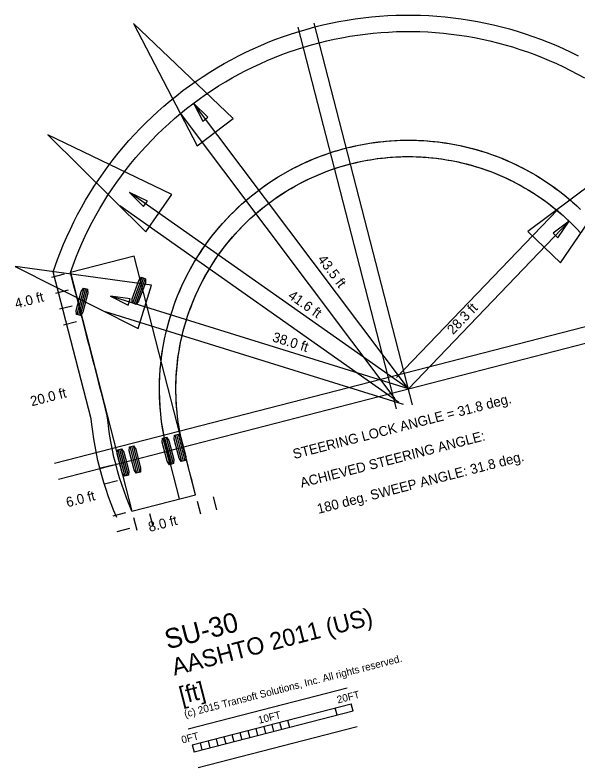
# Model space of a CAD drawing. Extents: x 916040 to 917457, y 328936 to 330267.
# Drawn here: x 916815.3 to 916883.8, y 329775.2 to 329866.9 of the extents above; entities that cross this region are included whole.
import ezdxf

# ---------------------------------------------------------------- set-up
doc = ezdxf.new("R2010")
doc.units = 0
doc.layers.add('SU_IntoDriveway', color=7, linetype='Continuous')

msp = doc.modelspace()

# ---------------------------------------------------------------- linework, layer by layer
at = {"layer": 'SU_IntoDriveway'}
for p, q in [((916863.656, 329819.438), (916851.67, 329865.925)), ((916861.719, 329818.939), (916849.734, 329865.426)), ((916863.156, 329821.375), (916836.984, 329856.161)), ((916861.558, 329820.172), (916835.385, 329854.959)), ((916863.156, 329821.375), (916829.176, 329845.317)), ((916862.004, 329819.74), (916828.024, 329843.682)), ((916861.713, 329822.759), (916881.3, 329843.183)), ((916863.156, 329821.375), (916882.743, 329841.799)), ((916829.742, 329837.545), (916821.995, 329835.548)), ((916837.231, 329808.495), (916829.742, 329837.545)), ((916821.22, 329835.348), (916819.671, 329834.948)), ((916821.995, 329835.548), (916829.485, 329806.497)), ((916821.995, 329835.548), (916821.995, 329835.548)), ((916830.699, 329834.958), (916829.559, 329831.826)), ((916830.895, 329834.887), (916829.755, 329831.755)), ((916831.091, 329834.816), (916829.951, 329831.683)), ((916820.043, 329812.325), (916905.271, 329834.298)), ((916823.627, 329833.654), (916822.767, 329830.433)), ((916823.828, 329833.6), (916822.968, 329830.379)), ((916824.029, 329833.546), (916823.169, 329830.326)), ((916821.72, 329833.411), (916820.17, 329833.012)), ((916863.156, 329821.375), (916826.867, 329832.673)), ((916820.542, 329810.388), (916905.77, 329832.361)), ((916822.219, 329831.474), (916820.67, 329831.075)), ((916862.562, 329819.465), (916826.272, 329830.763)), ((916822.718, 329829.538), (916821.169, 329829.138)), ((916833.26, 329815.388), (916834.092, 329812.16)), ((916833.461, 329815.44), (916834.293, 329812.212)), ((916833.663, 329815.492), (916834.495, 329812.264)), ((916834.712, 329815.763), (916835.544, 329812.535)), ((916834.914, 329815.815), (916835.746, 329812.587)), ((916835.116, 329815.867), (916835.948, 329812.639)), ((916829.225, 329814.348), (916830.057, 329811.12)), ((916829.427, 329814.4), (916830.259, 329811.172)), ((916829.628, 329814.452), (916830.46, 329811.224)), ((916827.772, 329813.973), (916828.604, 329810.746)), ((916827.974, 329814.025), (916828.806, 329810.798)), ((916828.176, 329814.077), (916829.008, 329810.85)), ((916827.212, 329812.108), (916825.663, 329811.708)), ((916827.711, 329810.171), (916826.162, 329809.772)), ((916829.485, 329806.497), (916837.231, 329808.495)), ((916839.368, 329808.219), (916839.767, 329806.67)), ((916837.431, 329807.72), (916837.83, 329806.171)), ((916828.71, 329806.298), (916827.161, 329805.898)), ((916831.621, 329806.222), (916832.02, 329804.673)), ((916829.684, 329805.723), (916830.084, 329804.173)), ((916829.209, 329804.361), (916827.66, 329803.962)), ((916836.325, 329779.965), (916855.692, 329784.958)), ((916836.824, 329778.028), (916856.191, 329783.021)), ((916856.416, 329782.15), (916856.191, 329783.021)), ((916856.416, 329782.15), (916837.049, 329777.157)), ((916854.479, 329781.651), (916854.254, 329782.522)), ((916845.539, 329780.275), (916845.764, 329779.404)), ((916845.539, 329780.275), (916845.764, 329779.404)), ((916846.508, 329780.525), (916846.732, 329779.653)), ((916846.508, 329780.525), (916846.732, 329779.653)), ((916847.476, 329780.775), (916847.701, 329779.903)), ((916848.444, 329781.024), (916848.669, 329780.153)), ((916856.915, 329780.213), (916837.548, 329775.22)), ((916842.634, 329779.526), (916842.859, 329778.655)), ((916842.634, 329779.526), (916842.859, 329778.655)), ((916843.603, 329779.776), (916843.827, 329778.904)), ((916843.603, 329779.776), (916843.827, 329778.904)), ((916844.571, 329780.026), (916844.796, 329779.154)), ((916844.571, 329780.026), (916844.796, 329779.154)), ((916838.761, 329778.528), (916838.986, 329777.656)), ((916838.761, 329778.528), (916838.986, 329777.656)), ((916839.729, 329778.777), (916839.954, 329777.906)), ((916839.729, 329778.777), (916839.954, 329777.906)), ((916840.698, 329779.027), (916840.922, 329778.156)), ((916840.698, 329779.027), (916840.922, 329778.156)), ((916841.666, 329779.277), (916841.891, 329778.405)), ((916841.666, 329779.277), (916841.891, 329778.405)), ((916836.824, 329778.028), (916837.049, 329777.157)), ((916837.793, 329778.278), (916838.017, 329777.407))]:
    msp.add_line(p, q, dxfattribs=at)
for points in [[(916827.636, 329805.734), (916827.302, 329806.543), (916826.965, 329807.379), (916826.643, 329808.237), (916826.336, 329809.116), (916826.068, 329809.99), (916825.811, 329810.854), (916825.571, 329811.738), (916825.349, 329812.641), (916825.164, 329813.532), (916824.991, 329814.408), (916824.832, 329815.31), (916824.711, 329816.192), (916824.598, 329817.048), (916824.517, 329817.752), (916819.905, 329835.642), (916820.439, 329837.139), (916820.795, 329838.071), (916821.171, 329838.996), (916821.567, 329839.912), (916821.984, 329840.82), (916822.42, 329841.717), (916822.876, 329842.606), (916823.351, 329843.484), (916823.845, 329844.351), (916824.358, 329845.207), (916824.89, 329846.052), (916825.44, 329846.885), (916826.008, 329847.706), (916826.594, 329848.514), (916827.198, 329849.309), (916827.819, 329850.09), (916828.457, 329850.858), (916829.112, 329851.612), (916829.783, 329852.351), (916830.47, 329853.075), (916831.173, 329853.784), (916831.891, 329854.478), (916832.624, 329855.155), (916833.372, 329855.816), (916834.134, 329856.461), (916834.911, 329857.089), (916835.7, 329857.7), (916836.503, 329858.293), (916837.319, 329858.868), (916838.147, 329859.426), (916838.988, 329859.965), (916839.839, 329860.486), (916840.702, 329860.987), (916841.576, 329861.47), (916842.461, 329861.934), (916843.355, 329862.378), (916844.259, 329862.802), (916845.171, 329863.206), (916846.093, 329863.591), (916847.022, 329863.955), (916847.96, 329864.298), (916848.905, 329864.621), (916849.856, 329864.923), (916850.814, 329865.204), (916851.778, 329865.464), (916852.747, 329865.703), (916853.722, 329865.921), (916854.701, 329866.117), (916855.684, 329866.292), (916856.67, 329866.445), (916857.66, 329866.576), (916858.652, 329866.686), (916859.647, 329866.773), (916860.643, 329866.839), (916861.641, 329866.884), (916862.639, 329866.906), (916863.637, 329866.906), (916864.635, 329866.885), (916865.633, 329866.842), (916866.629, 329866.776), (916867.624, 329866.689), (916868.616, 329866.58), (916869.606, 329866.45), (916870.593, 329866.298), (916871.576, 329866.124), (916872.555, 329865.928), (916873.53, 329865.712), (916874.499, 329865.474), (916875.463, 329865.214), (916876.422, 329864.934), (916877.373, 329864.633), (916878.318, 329864.31), (916879.256, 329863.968), (916880.186, 329863.604), (916881.108, 329863.221), (916882.021, 329862.817), (916882.925, 329862.394), (916883.82, 329861.95)], [(916829.485, 329806.497), (916829.154, 329807.299), (916828.829, 329808.105), (916828.523, 329808.918), (916828.237, 329809.739), (916827.983, 329810.568), (916827.735, 329811.401), (916827.507, 329812.239), (916827.299, 329813.083), (916827.125, 329813.929), (916826.957, 329814.776), (916826.809, 329815.62), (916826.693, 329816.459), (916826.583, 329817.293), (916826.489, 329818.118), (916826.275, 329818.948), (916826.061, 329819.778), (916825.847, 329820.608), (916825.633, 329821.438), (916825.419, 329822.268), (916825.205, 329823.098), (916824.991, 329823.928), (916824.777, 329824.758), (916824.563, 329825.588), (916824.349, 329826.418), (916824.135, 329827.248), (916823.921, 329828.078), (916823.707, 329828.908), (916823.493, 329829.738), (916823.279, 329830.568), (916823.065, 329831.398), (916822.851, 329832.228), (916822.637, 329833.058), (916822.423, 329833.888), (916822.209, 329834.718), (916821.995, 329835.548), (916821.995, 329835.548), (916822.316, 329836.446), (916822.656, 329837.338), (916823.015, 329838.222), (916823.394, 329839.098), (916823.792, 329839.965), (916824.209, 329840.824), (916824.645, 329841.673), (916825.099, 329842.512), (916825.572, 329843.342), (916826.062, 329844.16), (916826.571, 329844.968), (916827.097, 329845.764), (916827.64, 329846.549), (916828.2, 329847.322), (916828.778, 329848.082), (916829.371, 329848.829), (916829.981, 329849.563), (916830.607, 329850.284), (916831.249, 329850.99), (916831.906, 329851.683), (916832.578, 329852.361), (916833.264, 329853.024), (916833.965, 329853.671), (916834.68, 329854.304), (916835.409, 329854.92), (916836.151, 329855.52), (916836.906, 329856.104), (916837.674, 329856.671), (916838.454, 329857.221), (916839.246, 329857.754), (916840.049, 329858.27), (916840.864, 329858.768), (916841.689, 329859.247), (916842.524, 329859.709), (916843.37, 329860.152), (916844.225, 329860.577), (916845.089, 329860.982), (916845.961, 329861.369), (916846.842, 329861.736), (916847.731, 329862.084), (916848.627, 329862.413), (916849.531, 329862.721), (916850.44, 329863.01), (916851.356, 329863.279), (916852.278, 329863.528), (916853.205, 329863.756), (916854.136, 329863.964), (916855.072, 329864.152), (916856.012, 329864.319), (916856.955, 329864.465), (916857.902, 329864.59), (916858.85, 329864.695), (916859.801, 329864.779), (916860.754, 329864.842), (916861.707, 329864.885), (916862.661, 329864.906), (916863.616, 329864.906), (916864.57, 329864.886), (916865.524, 329864.844), (916866.477, 329864.782), (916867.427, 329864.699), (916868.376, 329864.595), (916869.323, 329864.47), (916870.266, 329864.324), (916871.206, 329864.158), (916872.142, 329863.971), (916873.074, 329863.764), (916874.001, 329863.536), (916874.923, 329863.289), (916875.839, 329863.02), (916876.749, 329862.732), (916877.652, 329862.424), (916878.549, 329862.097), (916879.438, 329861.749), (916880.319, 329861.383), (916881.193, 329860.997), (916882.057, 329860.592), (916882.912, 329860.168), (916883.758, 329859.726), (916884.594, 329859.265)], [(916833.791, 329813.829), (916833.638, 329814.454), (916833.494, 329815.103), (916833.364, 329815.755), (916833.249, 329816.41), (916833.148, 329817.067), (916833.061, 329817.726), (916832.989, 329818.387), (916832.931, 329819.049), (916832.888, 329819.712), (916832.859, 329820.376), (916832.845, 329821.041), (916832.846, 329821.706), (916832.861, 329822.37), (916832.891, 329823.034), (916832.935, 329823.697), (916832.993, 329824.36), (916833.066, 329825.02), (916833.154, 329825.679), (916833.256, 329826.336), (916833.372, 329826.99), (916833.503, 329827.642), (916833.648, 329828.29), (916833.807, 329828.936), (916833.98, 329829.577), (916834.167, 329830.215), (916834.368, 329830.848), (916834.583, 329831.477), (916834.812, 329832.101), (916835.054, 329832.72), (916835.31, 329833.333), (916835.579, 329833.941), (916835.862, 329834.543), (916836.157, 329835.138), (916836.466, 329835.726), (916836.787, 329836.308), (916837.121, 329836.882), (916837.467, 329837.449), (916837.826, 329838.009), (916838.197, 329838.56), (916838.58, 329839.103), (916838.975, 329839.638), (916839.381, 329840.163), (916839.799, 329840.68), (916840.228, 329841.187), (916840.668, 329841.685), (916841.119, 329842.173), (916841.58, 329842.651), (916842.052, 329843.119), (916842.534, 329843.577), (916843.026, 329844.023), (916843.528, 329844.459), (916844.038, 329844.884), (916844.559, 329845.297), (916845.088, 329845.699), (916845.625, 329846.09), (916846.172, 329846.468), (916846.726, 329846.834), (916847.288, 329847.188), (916847.858, 329847.53), (916848.435, 329847.859), (916849.02, 329848.175), (916849.611, 329848.479), (916850.208, 329848.769), (916850.812, 329849.046), (916851.422, 329849.31), (916852.037, 329849.561), (916852.658, 329849.798), (916853.283, 329850.021), (916853.914, 329850.231), (916854.549, 329850.426), (916855.188, 329850.608), (916855.831, 329850.775), (916856.477, 329850.929), (916857.127, 329851.068), (916857.779, 329851.193), (916858.435, 329851.304), (916859.092, 329851.4), (916859.751, 329851.482), (916860.412, 329851.549), (916861.074, 329851.602), (916861.738, 329851.641), (916862.402, 329851.664), (916863.066, 329851.674), (916863.73, 329851.668), (916864.394, 329851.648), (916865.058, 329851.614), (916865.72, 329851.565), (916866.382, 329851.501), (916867.042, 329851.423), (916867.699, 329851.331), (916868.355, 329851.224), (916869.008, 329851.103), (916869.659, 329850.967), (916870.306, 329850.818), (916870.95, 329850.654), (916871.59, 329850.476), (916872.226, 329850.284), (916872.858, 329850.078), (916873.485, 329849.858), (916874.107, 329849.625), (916874.724, 329849.378), (916875.335, 329849.118), (916875.94, 329848.844), (916876.539, 329848.557), (916877.132, 329848.257), (916877.718, 329847.944), (916878.297, 329847.619), (916878.869, 329847.28), (916879.433, 329846.93), (916879.99, 329846.567), (916880.538, 329846.191), (916881.078, 329845.804), (916881.609, 329845.405), (916882.132, 329844.995), (916882.645, 329844.573), (916883.149, 329844.14), (916883.643, 329843.697), (916884.128, 329843.242)], [(916835.295, 329807.995), (916833.793, 329813.821), (916833.581, 329814.7), (916833.394, 329815.598), (916833.234, 329816.501), (916833.101, 329817.409), (916832.995, 329818.32), (916832.918, 329819.235), (916832.867, 329820.151), (916832.845, 329821.068), (916832.85, 329821.985), (916832.883, 329822.902), (916832.944, 329823.817), (916833.032, 329824.73), (916833.148, 329825.64), (916833.292, 329826.546), (916833.462, 329827.447), (916833.66, 329828.342), (916833.885, 329829.232), (916834.136, 329830.113), (916834.415, 329830.987), (916834.719, 329831.852), (916835.049, 329832.708), (916835.405, 329833.553), (916835.787, 329834.387), (916836.193, 329835.209), (916836.624, 329836.018), (916837.08, 329836.814), (916837.559, 329837.595), (916838.059, 329838.359), (916838.441, 329838.908), (916838.832, 329839.446), (916839.234, 329839.976), (916839.648, 329840.496), (916840.073, 329841.007), (916840.51, 329841.509), (916840.957, 329842), (916841.415, 329842.482), (916841.883, 329842.954), (916842.362, 329843.416), (916842.851, 329843.866), (916843.349, 329844.306), (916843.857, 329844.735), (916844.374, 329845.153), (916844.9, 329845.559), (916845.435, 329845.954), (916845.979, 329846.336), (916846.531, 329846.707), (916847.09, 329847.066), (916847.658, 329847.412), (916848.233, 329847.745), (916848.815, 329848.066), (916849.404, 329848.374), (916849.999, 329848.669), (916850.601, 329848.951), (916851.209, 329849.22), (916851.822, 329849.475), (916852.441, 329849.717), (916853.066, 329849.945), (916853.695, 329850.159), (916854.328, 329850.36), (916854.966, 329850.546), (916855.608, 329850.719), (916856.253, 329850.877), (916856.902, 329851.022), (916857.554, 329851.152), (916858.208, 329851.267), (916858.865, 329851.369), (916859.524, 329851.455), (916860.184, 329851.528), (916860.846, 329851.586), (916861.509, 329851.629), (916862.173, 329851.658), (916862.837, 329851.672), (916863.502, 329851.672), (916864.166, 329851.657), (916864.83, 329851.627), (916865.493, 329851.583), (916866.155, 329851.525), (916866.815, 329851.452), (916867.474, 329851.364), (916868.131, 329851.262), (916868.785, 329851.146), (916869.436, 329851.015), (916870.085, 329850.871), (916870.73, 329850.712), (916871.371, 329850.538), (916872.009, 329850.351), (916872.642, 329850.15), (916873.271, 329849.935), (916873.895, 329849.706), (916874.513, 329849.464), (916875.126, 329849.208), (916875.734, 329848.939), (916876.335, 329848.657), (916876.93, 329848.361), (916877.519, 329848.053), (916878.1, 329847.731), (916878.675, 329847.397), (916879.241, 329847.051), (916879.801, 329846.692), (916880.352, 329846.321), (916880.895, 329845.938), (916881.429, 329845.543), (916881.954, 329845.136), (916882.471, 329844.718), (916882.978, 329844.289), (916883.476, 329843.849), (916883.964, 329843.398)], [(916835.733, 329814.305), (916835.586, 329814.908), (916835.451, 329815.514), (916835.33, 329816.124), (916835.222, 329816.735), (916835.128, 329817.349), (916835.047, 329817.965), (916834.979, 329818.582), (916834.926, 329819.201), (916834.885, 329819.82), (916834.859, 329820.441), (916834.845, 329821.061), (916834.846, 329821.682), (916834.86, 329822.303), (916834.888, 329822.923), (916834.929, 329823.543), (916834.984, 329824.161), (916835.052, 329824.778), (916835.134, 329825.394), (916835.229, 329826.007), (916835.338, 329826.618), (916835.46, 329827.227), (916835.595, 329827.833), (916835.744, 329828.436), (916835.905, 329829.035), (916836.08, 329829.631), (916836.268, 329830.222), (916836.469, 329830.81), (916836.682, 329831.392), (916836.909, 329831.97), (916837.148, 329832.543), (916837.399, 329833.111), (916837.663, 329833.673), (916837.939, 329834.229), (916838.227, 329834.778), (916838.527, 329835.322), (916838.839, 329835.858), (916839.162, 329836.388), (916839.498, 329836.91), (916839.844, 329837.425), (916840.202, 329837.932), (916840.571, 329838.432), (916840.95, 329838.923), (916841.34, 329839.405), (916841.741, 329839.879), (916842.152, 329840.344), (916842.573, 329840.8), (916843.004, 329841.247), (916843.445, 329841.684), (916843.895, 329842.111), (916844.354, 329842.528), (916844.823, 329842.935), (916845.3, 329843.332), (916845.786, 329843.718), (916846.28, 329844.093), (916846.782, 329844.458), (916847.292, 329844.811), (916847.81, 329845.153), (916848.335, 329845.484), (916848.868, 329845.803), (916849.407, 329846.111), (916849.952, 329846.406), (916850.504, 329846.689), (916851.063, 329846.961), (916851.627, 329847.22), (916852.196, 329847.466), (916852.771, 329847.7), (916853.351, 329847.921), (916853.935, 329848.13), (916854.524, 329848.326), (916855.117, 329848.508), (916855.714, 329848.678), (916856.314, 329848.835), (916856.918, 329848.978), (916857.525, 329849.108), (916858.134, 329849.225), (916858.746, 329849.328), (916859.36, 329849.418), (916859.976, 329849.495), (916860.593, 329849.558), (916861.212, 329849.607), (916861.831, 329849.643), (916862.451, 329849.665), (916863.072, 329849.674), (916863.692, 329849.669), (916864.313, 329849.65), (916864.932, 329849.618), (916865.551, 329849.572), (916866.169, 329849.513), (916866.785, 329849.44), (916867.399, 329849.353), (916868.012, 329849.254), (916868.622, 329849.14), (916869.229, 329849.014), (916869.834, 329848.874), (916870.435, 329848.721), (916871.033, 329848.555), (916871.627, 329848.376), (916872.217, 329848.183), (916872.803, 329847.978), (916873.384, 329847.76), (916873.96, 329847.53), (916874.531, 329847.286), (916875.096, 329847.031), (916875.656, 329846.763), (916876.209, 329846.483), (916876.757, 329846.19), (916877.298, 329845.886), (916877.832, 329845.57), (916878.359, 329845.243), (916878.878, 329844.904), (916879.39, 329844.553), (916879.895, 329844.192), (916880.391, 329843.819), (916880.879, 329843.436), (916881.358, 329843.042), (916881.829, 329842.638), (916882.291, 329842.223), (916882.743, 329841.799), (916883.191, 329841.36), (916883.637, 329840.903), (916884.082, 329840.429)], [(916837.231, 329808.495), (916837.017, 329809.325), (916836.803, 329810.155), (916836.589, 329810.985), (916836.375, 329811.815), (916836.161, 329812.645), (916835.947, 329813.475), (916835.733, 329814.305), (916835.533, 329815.138), (916835.358, 329815.977), (916835.208, 329816.821), (916835.084, 329817.669), (916834.986, 329818.52), (916834.913, 329819.374), (916834.866, 329820.23), (916834.845, 329821.086), (916834.85, 329821.943), (916834.881, 329822.799), (916834.938, 329823.654), (916835.02, 329824.507), (916835.128, 329825.357), (916835.262, 329826.203), (916835.422, 329827.045), (916835.606, 329827.882), (916835.816, 329828.712), (916836.051, 329829.536), (916836.311, 329830.352), (916836.595, 329831.16), (916836.904, 329831.959), (916837.237, 329832.748), (916837.593, 329833.527), (916837.973, 329834.295), (916838.375, 329835.051), (916838.801, 329835.794), (916839.248, 329836.524), (916839.718, 329837.24), (916839.718, 329837.24), (916839.718, 329837.24), (916840.072, 329837.751), (916840.437, 329838.253), (916840.813, 329838.747), (916841.199, 329839.233), (916841.597, 329839.711), (916842.004, 329840.179), (916842.422, 329840.639), (916842.85, 329841.089), (916843.287, 329841.53), (916843.734, 329841.96), (916844.191, 329842.382), (916844.656, 329842.792), (916845.131, 329843.193), (916845.614, 329843.583), (916846.105, 329843.962), (916846.605, 329844.331), (916847.112, 329844.688), (916847.628, 329845.035), (916848.15, 329845.37), (916848.68, 329845.693), (916849.217, 329846.004), (916849.761, 329846.304), (916850.311, 329846.592), (916850.867, 329846.867), (916851.429, 329847.131), (916851.997, 329847.382), (916852.57, 329847.62), (916853.149, 329847.846), (916853.732, 329848.059), (916854.319, 329848.259), (916854.911, 329848.447), (916855.507, 329848.621), (916856.106, 329848.782), (916856.709, 329848.93), (916857.315, 329849.065), (916857.923, 329849.186), (916858.535, 329849.294), (916859.148, 329849.389), (916859.763, 329849.47), (916860.38, 329849.537), (916860.998, 329849.591), (916861.618, 329849.632), (916862.238, 329849.659), (916862.858, 329849.672), (916863.479, 329849.672), (916864.099, 329849.658), (916864.719, 329849.63), (916865.339, 329849.589), (916865.957, 329849.535), (916866.574, 329849.466), (916867.189, 329849.385), (916867.802, 329849.289), (916868.413, 329849.181), (916869.022, 329849.059), (916869.627, 329848.923), (916870.23, 329848.775), (916870.829, 329848.613), (916871.424, 329848.438), (916872.016, 329848.251), (916872.603, 329848.05), (916873.186, 329847.836), (916873.763, 329847.61), (916874.336, 329847.371), (916874.904, 329847.12), (916875.465, 329846.856), (916876.021, 329846.58), (916876.571, 329846.292), (916877.114, 329845.991), (916877.65, 329845.679), (916878.18, 329845.356), (916878.702, 329845.021), (916879.216, 329844.674), (916879.724, 329844.316), (916880.223, 329843.947), (916880.713, 329843.568), (916881.196, 329843.177), (916881.67, 329842.777), (916882.134, 329842.366), (916882.59, 329841.944), (916883.036, 329841.513), (916883.474, 329841.073), (916883.902, 329840.624)]]:
    msp.add_lwpolyline(points, dxfattribs=at)
for points in [[(916829.67, 329865.883), (916837.423, 329850.986), (916841.835, 329854.305)], [(916836.984, 329856.161), (916838.107, 329854.003), (916838.746, 329854.484)], [(916819.231, 329852.324), (916831.183, 329840.525), (916834.363, 329845.039)], [(916891.164, 329850.579), (916877.705, 329840.534), (916881.69, 329836.712)], [(916829.176, 329845.317), (916830.908, 329843.607), (916831.368, 329844.261)], [(916882.743, 329841.799), (916880.793, 329840.343), (916881.371, 329839.79)], [(916815.251, 329836.289), (916830.247, 329828.729), (916831.889, 329834.001)], [(916830.65, 329834.976), (916831.139, 329834.798), (916831.127, 329834.306), (916830.306, 329832.051), (916829.999, 329831.666), (916829.511, 329831.844), (916829.523, 329832.336), (916830.344, 329834.591)], [(916823.577, 329833.667), (916824.079, 329833.533), (916824.11, 329833.042), (916823.491, 329830.723), (916823.219, 329830.312), (916822.717, 329830.447), (916822.686, 329830.938), (916823.305, 329833.257)], [(916826.867, 329832.673), (916829.04, 329831.577), (916829.277, 329832.341)], [(916833.209, 329815.375), (916833.713, 329815.505), (916833.981, 329815.092), (916834.58, 329812.768), (916834.545, 329812.277), (916834.042, 329812.147), (916833.773, 329812.56), (916833.174, 329814.884)], [(916834.662, 329815.75), (916835.166, 329815.879), (916835.434, 329815.467), (916836.033, 329813.143), (916835.998, 329812.652), (916835.494, 329812.522), (916835.226, 329812.935), (916834.627, 329815.259)], [(916829.175, 329814.335), (916829.678, 329814.465), (916829.947, 329814.052), (916830.546, 329811.728), (916830.51, 329811.237), (916830.007, 329811.107), (916829.739, 329811.52), (916829.14, 329813.844)], [(916827.722, 329813.961), (916828.226, 329814.09), (916828.494, 329813.678), (916829.093, 329811.354), (916829.058, 329810.863), (916828.554, 329810.733), (916828.286, 329811.145), (916827.687, 329813.47)]]:
    msp.add_lwpolyline(points, close=True, dxfattribs=at)

# ---------------------------------------------------------------- texts
for s, height, rotation, p in [('43.5 ft', 1.2, 306.95691, (916852.039, 329837.149)), ('4.0 ft', 1.2, 14.45691, (916815.395, 329831.161)), ('41.6 ft', 1.2, 324.83191, (916848.403, 329832.504)), ('28.3 ft', 1.2, 46.19814, (916868.599, 329827.917)), ('38.0 ft', 1.2, 342.70691, (916846.501, 329827.189)), ('20.0 ft', 1.2, 14.45691, (916817.285, 329819.256)), ('STEERING LOCK ANGLE = 31.8 deg.', 1.2, 14.45691, (916849.249, 329812.832)), ('ACHIEVED STEERING ANGLE:', 1.2, 14.45691, (916850.147, 329809.346)), ('180 deg. SWEEP ANGLE: 31.8 deg.', 1.2, 14.45691, (916852.208, 329806.16)), ('6.0 ft', 1.2, 14.45691, (916821.637, 329806.953)), ('8.0 ft', 1.2, 14.45691, (916831.645, 329803.956)), ('SU-30', 2.4, 14.45691, (916833.828, 329789.648)), ('AASHTO 2011 (US)', 2.1, 14.45691, (916834.652, 329786.453)), ('(c) 2015 Transoft Solutions, Inc. All rights reserved.', 0.9, 14.45691, (916835.971, 329781.34)), ('[ft]', 2.1, 14.45691, (916835.551, 329782.967)), ('20FT', 0.9, 14.45691, (916854.585, 329783.072)), ('10FT', 0.9, 14.45691, (916844.984, 329780.597)), ('0FT', 0.9, 14.45691, (916835.633, 329778.186))]:
    msp.add_text(s, height=height, rotation=rotation, dxfattribs=at).set_placement(p)

doc.saveas('drawing.dxf')
